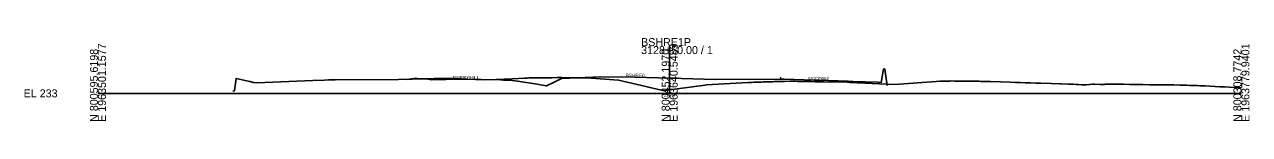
# Model space of a CAD drawing. Extents: x -26 to 403, y -10 to 6039.
# Drawn here: x -25.7 to 402.8, y -9.7 to 19.4 of the extents above; entities that cross this region are included whole.
import ezdxf

# ---------------------------------------------------------------- set-up
doc = ezdxf.new("R2010")
doc.units = 0
for name, color, linetype in [('Default', 7, 'Continuous'), ('RD_GPK_XS_Cell', 7, 'Continuous'), ('RD_TX_Misc1', 7, 'Continuous'), ('RD_XS_ExGround', 7, 'Continuous'), ('RD_XS_Pave', 7, 'Continuous'), ('RD_XS_TX_Elev_EX', 7, 'Continuous')]:
    doc.layers.add(name, color=color, linetype=linetype)

msp = doc.modelspace()

# ---------------------------------------------------------------- linework, layer by layer
at = {"layer": 'RD_GPK_XS_Cell'}
for p, q in [((200, 0), (200, 16.55)), ((0, 0), (200, 0)), ((200, 0), (400, 0))]:
    msp.add_line(p, q, dxfattribs=at)
at = {"layer": 'RD_XS_ExGround'}
msp.add_lwpolyline([(47.19, 0.79), (47.81, 0.89), (48.32, 5.21), (53.19, 4.1), (54.36, 3.77), (55.53, 3.69), (75.22, 4.49), (79.23, 4.63), (80.7, 4.7), (82.99, 4.75), (105.14, 4.86), (109.87, 5), (121.45, 5.28), (132.06, 4.84), (134.84, 4.73), (139.36, 4.87), (144.92, 5.09), (149.18, 5.26), (150.13, 5.34), (150.69, 5.39), (151.4, 5.43), (151.98, 5.44), (154.07, 5.46), (154.73, 5.46), (155.41, 5.47), (157.63, 5.49), (158.81, 5.49), (160.62, 5.51), (161.59, 5.52), (162.28, 5.51), (163.51, 5.49), (164.82, 5.48), (165.34, 5.47), (165.85, 5.47), (168.36, 5.44), (169.25, 5.42), (171.7, 5.39), (172.03, 5.38), (172.57, 5.32), (182.11, 4.64), (189.73, 2.87), (198.09, 0.9), (200, 1.17), (212.38, 2.91), (212.9, 2.94), (227.4, 3.79), (228.73, 3.83), (229.4, 3.86), (232.1, 3.95), (232.82, 3.98), (233.9, 4.02), (234.22, 4.03), (235.58, 4.06), (236.07, 4.08), (236.57, 4.09), (237.82, 4.13), (239.06, 4.16), (239.6, 4.17), (240.15, 4.19), (242.1, 4.23), (242.66, 4.22), (243.72, 4.21), (244.88, 4.19), (245.98, 4.17), (247.59, 4.15), (248.05, 4.14), (248.43, 4.13), (249.52, 4.1), (250.88, 4.06), (252.64, 4.01), (253.67, 4.03), (253.79, 4.02), (262.08, 3.88), (263.03, 3.84), (273.38, 3.35), (278.66, 3.09), (293.28, 4.13), (294.52, 4.22), (295.04, 4.24), (296.06, 4.25), (296.44, 4.29), (297.09, 4.3), (297.95, 4.32), (298.3, 4.33), (299.7, 4.32), (301.16, 4.31), (301.48, 4.31), (301.78, 4.31), (303.48, 4.29), (304.8, 4.28), (305.27, 4.27), (308.28, 4.22), (308.76, 4.2), (311.9, 4.11), (312.24, 4.1), (315.7, 3.99), (319.08, 3.89), (320.93, 3.83), (322.69, 3.77), (324.41, 3.71), (326.18, 3.65), (327.96, 3.59), (329.81, 3.54), (333.41, 3.45), (336.62, 3.34), (337.01, 3.33), (339.4, 3.27), (339.96, 3.25), (340.3, 3.23), (340.61, 3.21), (341.1, 3.18), (342.37, 3.11), (342.58, 3.07), (342.89, 3.06), (344.13, 3.02), (345.13, 3.03), (345.78, 3.03), (347.9, 3.16), (348.6, 3.2), (350.62, 3.14), (351.02, 3.13), (351.59, 3.14), (352.05, 3.14), (352.38, 3.21), (352.74, 3.22), (354.09, 3.24), (354.7, 3.25), (355.12, 3.24), (356.27, 3.22), (357.57, 3.19), (358.72, 3.17), (360.98, 3.14), (362.03, 3.12), (363.3, 3.1), (364.5, 3.07), (365.02, 3.06), (365.49, 3.06), (367.99, 3.03), (368.59, 3.03), (369.18, 3.03), (371.47, 3.01), (372.89, 3), (374.95, 2.97), (376.42, 2.95), (378.49, 2.9), (379.82, 2.86), (380.9, 2.82), (381.96, 2.79), (382.85, 2.76), (383.8, 2.72), (384.66, 2.69), (385.45, 2.65), (387.34, 2.58), (388.94, 2.5), (390.79, 2.4), (392.42, 2.32), (394.26, 2.24), (395.89, 2.16), (397.76, 2.07), (398.59, 2.04), (399.39, 2), (400, 1.97)], dxfattribs=at)
at = {"layer": 'RD_XS_Pave'}
for points in [[(108.01, 4.85), (110.64, 5.21), (111.84, 5.16), (113.66, 5.1), (115.46, 4.91), (116.67, 4.78), (121.68, 4.86), (128.73, 4.97), (134.02, 4.85), (140.78, 4.69), (141.88, 4.66), (142.79, 4.64), (144.96, 4.46), (146.81, 4.3), (152.1, 3.4), (156.86, 2.59), (159.58, 3.94), (162.63, 5.44)], [(162.27, 5.19), (175.83, 5.74), (187.83, 5.72), (200.12, 5.36), (216, 4.9), (239.66, 4.93), (240.02, 4.92)], [(238.68, 5.48), (238.82, 5.48), (238.9, 4.96), (240.02, 4.92), (250.59, 4.61), (252.02, 4.56), (262.5, 4.25), (264.03, 4.2), (272.7, 3.86), (274.03, 3.8), (274.78, 8.47), (275.28, 8.47), (276.03, 2.8)]]:
    msp.add_lwpolyline(points, dxfattribs=at)

# ---------------------------------------------------------------- texts
at = {"layer": 'Default'}
msp.add_text('-', height=0.0001, dxfattribs=at).set_placement((0, 0))
at = {"layer": 'RD_GPK_XS_Cell'}
for s, p in [('E 1963501.1577', (2.8, -10)), ('E 1963640.5489', (202.8, -10)), ('E 1963779.9401', (402.8, -10)), ('N 800595.6198', (0, -10)), ('N 800452.1970', (200, -10)), ('N 800308.7742', (400, -10))]:
    msp.add_text(s, height=2.8, rotation=90, dxfattribs=at).set_placement(p)
for s, p in [('BSHRE1P', (190, 16.55)), ('3128+50.00 / 1', (190, 13.75)), ('EL 233', (-26, -1.4))]:
    msp.add_text(s, height=2.8, dxfattribs=at).set_placement(p)
at = {"layer": 'RD_TX_Misc1'}
for s, p in [('BERRYHILL', (124.22, 4.93)), ('BSHRE0', (184.6, 5.72)), ('I20CDW2', (248.52, 4.57))]:
    msp.add_text(s, height=1.2, dxfattribs=at).set_placement(p)
at = {"layer": 'RD_XS_TX_Elev_EX'}
msp.add_text('234.17', height=1, dxfattribs=at).set_placement((197.9, -1.33))

doc.saveas('drawing.dxf')
